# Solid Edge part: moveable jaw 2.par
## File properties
Author: CADSoft
Template: Normal.par
Last saved by: TIET
Revision: 5
Application: Solid Edge
Accuracy: 0.990
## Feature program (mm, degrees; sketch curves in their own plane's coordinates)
sketch for "unnamed Protrusion 1" plane through (0, 0, 0) normal (0, -1, 0) x-axis (1, 0, 0)
  line (2.077, -7.5) -> (2.077, 52.5)
  line (2.077, 52.5) -> (-32.423, 52.5)
  line (-32.423, 52.5) -> (-32.423, -7.5)
  line (-28.923, -7.5) -> (-32.423, -7.5)
  line (-28.923, -5) -> (-28.923, -7.5)
  line (-28.923, -5) -> (-26.423, -5)
  line (-26.423, -5) -> (-26.423, -2.5)
  line (-26.423, -2.5) -> (-23.923, -2.5)
  line (-23.923, -2.5) -> (-23.923, 0)
  line (-23.923, 0) -> (-21.423, 0)
  line (-21.423, 0) -> (-21.423, 2.5)
  line (-21.423, 2.5) -> (-18.923, 2.5)
  line (-18.923, 2.5) -> (-18.923, 5)
  line (-18.923, 5) -> (-16.423, 5)
  line (-16.423, 5) -> (-16.423, 7.5)
  line (-16.423, 7.5) -> (-15.173, 7.5)
  line (-13.923, 7.5) -> (-15.173, 7.5)
  line (-13.923, 5) -> (-13.923, 7.5)
  line (-11.423, 5) -> (-13.923, 5)
  line (-11.423, 2.5) -> (-11.423, 5)
  line (-8.923, 2.5) -> (-11.423, 2.5)
  line (-8.923, 0) -> (-8.923, 2.5)
  line (-6.423, 0) -> (-8.923, 0)
  line (-6.423, -2.5) -> (-6.423, 0)
  line (-3.923, -2.5) -> (-6.423, -2.5)
  line (-3.923, -5) -> (-3.923, -2.5)
  line (-1.423, -5) -> (-3.923, -5)
  line (-1.423, -5) -> (-1.423, -7.5)
  line (-1.423, -7.5) -> (2.077, -7.5)
extrude "unnamed Protrusion 1" add finite 18 symmetric
sketch for "Hole_1" plane through (-15.173, 0, 52.5) normal (0, 0, 1) x-axis (-1, 0, 0)
  hole centre (0, 0) bore radius 6
hole "Hole_1" diameter 12 finite  VBottomAngle = 120 deg
sketch for "Hole_2" plane through (2.077, 0, 22.5) normal (1, 0, 0) x-axis (0, 1, 0)
  hole centre (0, 23) bore radius 3
hole "Hole_2" diameter 6 through
chamfer "Chamfer_2" setback 2
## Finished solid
Body 1: solid body, 38 faces, 98 edges, 60 vertices.
  Faces by surface: plane 34, cylinder 3, cone 1
  Edges by curve: line 92, circle 4, intersection 2
Bounding box of the edges (mm): 34.500 x 18.000 x 60.000, from (-32.423, -9, -7.5) to (2.077, 9, 52.5).
Cylindrical faces by radius (mm): R3 x2, R6 x1
Conical faces (half-angle, radius in mm at the cone's reference point): 60 deg R6 x1
Planar faces by outward normal: +x 7, +y 1, +z 1, -x 7, -y 1, -z 13, oblique 4
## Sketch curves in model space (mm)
line (-26.423, 0, -5) -> (-26.423, 0, -2.5)
line (-26.423, 0, -2.5) -> (-23.923, 0, -2.5)
line (-23.923, 0, -2.5) -> (-23.923, 0, 0)
line (-23.923, 0, 0) -> (-21.423, 0, 0)
line (-21.423, 0, 0) -> (-21.423, 0, 2.5)
line (-21.423, 0, 2.5) -> (-18.923, 0, 2.5)
line (-18.923, 0, 2.5) -> (-18.923, 0, 5)
line (-18.923, 0, 5) -> (-16.423, 0, 5)
line (-16.423, 0, 5) -> (-16.423, 0, 7.5)
line (-16.423, 0, 7.5) -> (-15.173, 0, 7.5)
line (-13.923, 0, 7.5) -> (-15.173, 0, 7.5)
line (-13.923, 0, 5) -> (-13.923, 0, 7.5)
line (-11.423, 0, 5) -> (-13.923, 0, 5)
line (-11.423, 0, 2.5) -> (-11.423, 0, 5)
line (-8.923, 0, 2.5) -> (-11.423, 0, 2.5)
line (-8.923, 0, 0) -> (-8.923, 0, 2.5)
line (-6.423, 0, 0) -> (-8.923, 0, 0)
line (-6.423, 0, -2.5) -> (-6.423, 0, 0)
line (-3.923, 0, -2.5) -> (-6.423, 0, -2.5)
line (-3.923, 0, -5) -> (-3.923, 0, -2.5)
line (-1.423, 0, -5) -> (-3.923, 0, -5)
line (-1.423, 0, -5) -> (-1.423, 0, -7.5)
line (-1.423, 0, -7.5) -> (2.077, 0, -7.5)
line (2.077, 0, -7.5) -> (2.077, 0, 52.5)
line (2.077, 0, 52.5) -> (-32.423, 0, 52.5)
line (-32.423, 0, 52.5) -> (-32.423, 0, -7.5)
line (-28.923, 0, -7.5) -> (-32.423, 0, -7.5)
line (-28.923, 0, -5) -> (-28.923, 0, -7.5)
line (-28.923, 0, -5) -> (-26.423, 0, -5)
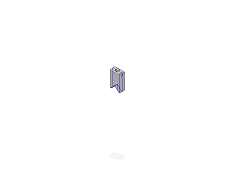
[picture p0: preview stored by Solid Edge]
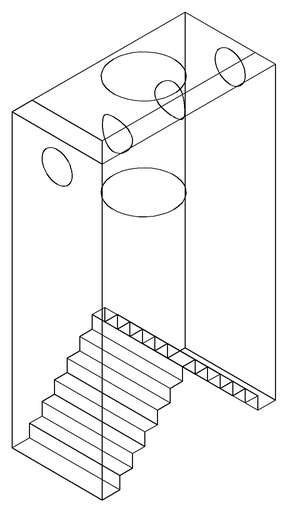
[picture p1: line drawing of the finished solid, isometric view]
